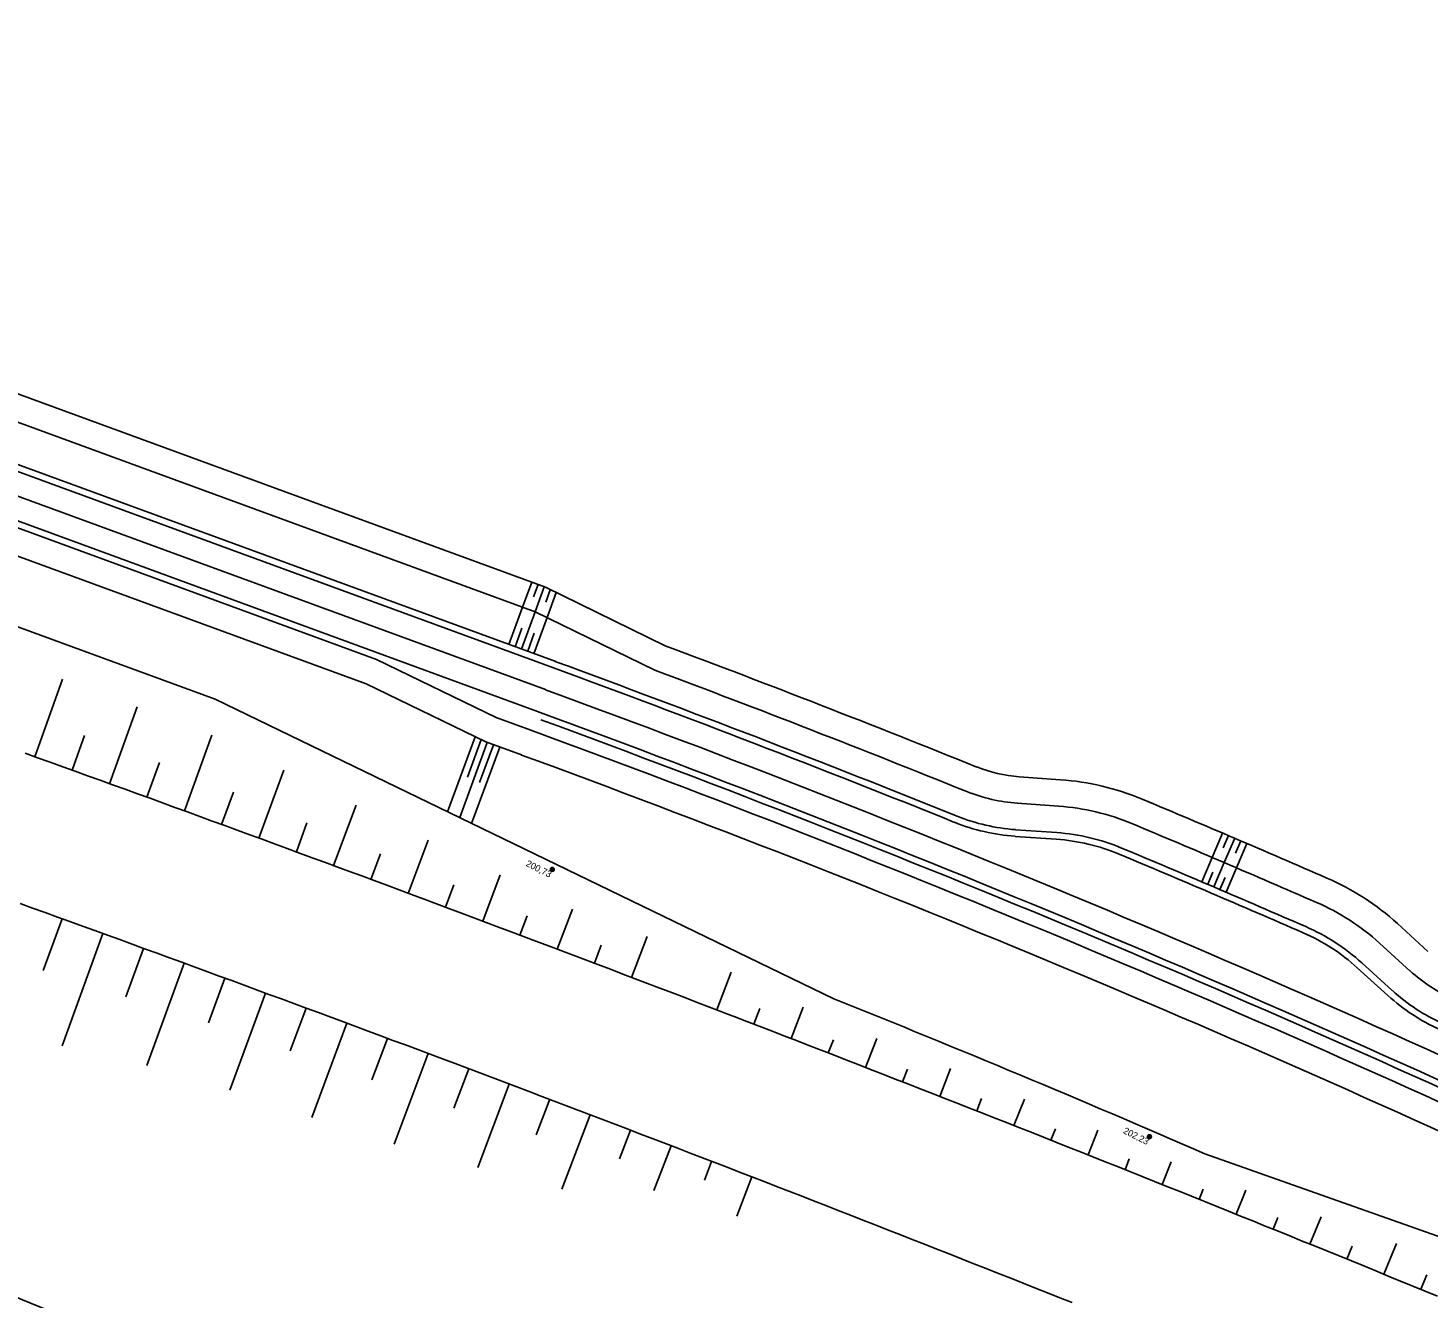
# Model space of a CAD drawing. Extents: x -552278 to -547230, y -1151007 to -1148251.
# Drawn here: x -550769.8 to -550664.2, y -1148841.8 to -1148746 of the extents above; entities that cross this region are included whole.
import ezdxf

# ---------------------------------------------------------------- set-up
doc = ezdxf.new("R2010")
doc.units = 0
doc.layers.add('SO221815_VYSKOPIS', color=7, linetype='Continuous')
doc.layers.add('u_trat navrh', color=7, linetype='Continuous')

# ---------------------------------------------------------------- blocks, each defined once
blk = doc.blocks.new('SO221824_VYSKOPIS')
at = {"layer": 'SO221815_VYSKOPIS'}
for p, q in [((1.2, -0.9), (-1.2, 0.9)), ((0.9, 1.2), (-0.9, -1.2)), ((0.9, 1.2), (0, 0)), ((0, 0), (1.2, -0.9))]:
    blk.add_line(p, q, dxfattribs=at)
blk.add_lwpolyline([(-0.9, -1.2), (0, 0), (-1.2, 0.9)], dxfattribs=at)
blk.add_circle((0, 0), 1.5, dxfattribs=at)
for start, end in [(145.362, 235.1538), (325.362, 55.1538)]:
    blk.add_arc((0, 0), 1.5, start, end, dxfattribs=at)

msp = doc.modelspace()

# ---------------------------------------------------------------- linework, layer by layer
at = {"layer": 'u_trat navrh'}
for p, q in [((-550730.77, -1148788.22), (-550845.88, -1148746.02)), ((-550731.56, -1148790.07), (-550846.57, -1148747.9)), ((-550730.17, -1148794.3), (-550847.77, -1148751.19)), ((-550730, -1148793.83), (-550847.6, -1148750.72)), ((-550730.77, -1148795.94), (-550848.38, -1148752.83)), ((-550743.53, -1148793.66), (-550849.15, -1148754.94)), ((-550731.38, -1148797.59), (-550848.98, -1148754.47)), ((-550744.31, -1148795.51), (-550849.84, -1148756.82)), ((-550732.5, -1148789.72), (-550731.81, -1148787.84)), ((-550731.68, -1148788.95), (-550731.34, -1148788.02)), ((-550731.56, -1148790.07), (-550730.87, -1148788.19)), ((-550721.74, -1148792.63), (-550730.77, -1148788.22)), ((-550730.76, -1148789.34), (-550730.42, -1148788.4)), ((-550730.66, -1148790.51), (-550729.96, -1148788.62)), ((-550755.7, -1148796.66), (-550774.11, -1148789.91)), ((-550733.53, -1148792.54), (-550732.5, -1148789.72)), ((-550732.59, -1148792.88), (-550731.56, -1148790.07)), ((-550722.53, -1148794.47), (-550731.56, -1148790.07)), ((-550733.06, -1148792.71), (-550732.55, -1148791.3)), ((-550731.65, -1148793.23), (-550730.66, -1148790.51)), ((-550732.12, -1148793.05), (-550731.62, -1148791.67)), ((-550743.53, -1148793.66), (-550734.49, -1148798.05)), ((-550769.31, -1148801), (-550767.22, -1148795.16)), ((-550744.31, -1148795.51), (-550735.27, -1148799.89)), ((-550763.67, -1148803.04), (-550761.57, -1148797.23)), ((-550755.7, -1148796.66), (-550709.03, -1148819.26)), ((-550731.89, -1148799), (-550734.49, -1148798.05)), ((-550766.49, -1148802.02), (-550765.55, -1148799.4)), ((-550758.02, -1148805.08), (-550755.95, -1148799.38)), ((-550736.08, -1148799.49), (-550738.16, -1148805.16)), ((-550735.63, -1148799.71), (-550736.67, -1148802.54)), ((-550735.17, -1148799.92), (-550737.25, -1148805.59)), ((-550734.23, -1148800.27), (-550736.35, -1148806.03)), ((-550734.7, -1148800.1), (-550735.75, -1148802.95)), ((-550732.58, -1148800.87), (-550735.27, -1148799.89)), ((-550760.84, -1148804.06), (-550759.9, -1148801.45)), ((-550752.39, -1148807.14), (-550750.51, -1148802.02)), ((-550695.04, -1148802.52), (-550691.92, -1148802.74)), ((-550755.21, -1148806.11), (-550754.32, -1148803.68)), ((-550746.76, -1148809.22), (-550745.07, -1148804.65)), ((-550695.18, -1148804.51), (-550692.06, -1148804.73)), ((-550749.57, -1148808.18), (-550748.77, -1148806)), ((-550695.35, -1148807.01), (-550692.24, -1148807.23)), ((-550695.32, -1148806.51), (-550692.2, -1148806.73)), ((-550680.49, -1148808.6), (-550679.7, -1148806.76)), ((-550679.64, -1148807.87), (-550679.24, -1148806.95)), ((-550679.57, -1148808.99), (-550678.78, -1148807.15)), ((-550741.13, -1148811.31), (-550739.63, -1148807.29)), ((-550678.72, -1148808.27), (-550678.32, -1148807.35)), ((-550678.65, -1148809.38), (-550677.86, -1148807.54)), ((-550743.94, -1148810.26), (-550743.23, -1148808.33)), ((-550681.27, -1148810.44), (-550680.49, -1148808.6)), ((-550680.35, -1148810.83), (-550679.57, -1148808.99)), ((-550735.51, -1148813.41), (-550734.2, -1148809.92)), ((-550680.81, -1148810.63), (-550680.42, -1148809.71)), ((-550679.89, -1148811.03), (-550679.5, -1148810.11)), ((-550679.43, -1148811.22), (-550678.65, -1148809.38)), ((-550738.32, -1148812.35), (-550737.69, -1148810.67)), ((-550767.25, -1148813.23), (-550768.66, -1148817.14)), ((-550732.7, -1148814.46), (-550732.15, -1148813.01)), ((-550729.89, -1148815.52), (-550728.75, -1148812.5)), ((-550764.17, -1148814.34), (-550767.25, -1148822.82)), ((-550724.28, -1148817.65), (-550723.11, -1148814.57)), ((-550666.51, -1148813.59), (-550664.2, -1148815.69)), ((-550761.1, -1148815.46), (-550762.43, -1148819.11)), ((-550727.08, -1148816.58), (-550726.57, -1148815.21)), ((-550667.85, -1148815.07), (-550665.54, -1148817.17)), ((-550758.03, -1148816.58), (-550760.86, -1148824.3)), ((-550669.2, -1148816.55), (-550666.89, -1148818.65)), ((-550754.96, -1148817.7), (-550756.2, -1148821.08)), ((-550717.86, -1148820.1), (-550716.77, -1148817.25)), ((-550669.53, -1148816.92), (-550667.22, -1148819.02)), ((-550751.89, -1148818.83), (-550754.59, -1148826.15)), ((-550748.83, -1148819.97), (-550750.03, -1148823.2)), ((-550715.05, -1148821.18), (-550714.6, -1148820.01)), ((-550712.25, -1148822.26), (-550711.33, -1148819.89)), ((-550745.76, -1148821.11), (-550748.4, -1148828.21)), ((-550742.7, -1148822.25), (-550743.87, -1148825.39)), ((-550709.44, -1148823.35), (-550709.05, -1148822.35)), ((-550706.64, -1148824.44), (-550705.79, -1148822.25)), ((-550739.63, -1148823.39), (-550742.2, -1148830.23)), ((-550736.57, -1148824.54), (-550737.69, -1148827.51)), ((-550703.84, -1148825.53), (-550703.46, -1148824.57)), ((-550701.03, -1148826.63), (-550700.21, -1148824.53)), ((-550733.51, -1148825.7), (-550735.89, -1148831.99)), ((-550730.46, -1148826.85), (-550731.47, -1148829.54)), ((-550698.23, -1148827.73), (-550697.87, -1148826.8)), ((-550695.44, -1148828.83), (-550694.65, -1148826.84)), ((-550727.4, -1148828.02), (-550729.54, -1148833.63)), ((-550724.35, -1148829.18), (-550725.18, -1148831.35)), ((-550692.64, -1148829.94), (-550692.29, -1148829.07)), ((-550689.84, -1148831.05), (-550689.1, -1148829.18)), ((-550721.29, -1148830.35), (-550722.6, -1148833.74)), ((-550687.05, -1148832.16), (-550686.73, -1148831.35)), ((-550681.03, -1148830.96), (-550658.23, -1148839.02)), ((-550718.24, -1148831.53), (-550718.79, -1148832.94)), ((-550684.25, -1148833.28), (-550683.57, -1148831.56)), ((-550715.21, -1148832.7), (-550716.35, -1148835.66)), ((-550681.46, -1148834.4), (-550681.16, -1148833.63)), ((-550678.67, -1148835.52), (-550677.94, -1148833.71)), ((-550673.1, -1148837.77), (-550672.26, -1148835.72)), ((-550675.88, -1148836.64), (-550675.53, -1148835.77)), ((-550667.52, -1148840.04), (-550666.58, -1148837.73)), ((-550670.31, -1148838.91), (-550669.91, -1148837.92)), ((-550664.74, -1148841.18), (-550664.29, -1148840.08))]:
    msp.add_line(p, q, dxfattribs=at)
for points in [[(-550770.03, -1148800.74), (-550769.09, -1148801.08), (-550768.15, -1148801.42), (-550767.2, -1148801.76), (-550766.26, -1148802.1), (-550765.32, -1148802.44), (-550764.38, -1148802.78), (-550763.44, -1148803.12), (-550762.49, -1148803.46), (-550761.55, -1148803.8), (-550760.61, -1148804.14), (-550759.67, -1148804.48), (-550758.73, -1148804.83), (-550757.79, -1148805.17), (-550756.85, -1148805.51), (-550755.91, -1148805.86), (-550754.97, -1148806.2), (-550754.03, -1148806.54), (-550753.09, -1148806.89), (-550752.15, -1148807.23), (-550751.21, -1148807.58), (-550750.27, -1148807.92), (-550749.33, -1148808.27), (-550748.39, -1148808.62), (-550747.45, -1148808.96), (-550746.51, -1148809.31), (-550745.57, -1148809.66), (-550744.63, -1148810), (-550743.69, -1148810.35), (-550742.75, -1148810.7), (-550741.81, -1148811.05), (-550740.88, -1148811.4), (-550739.94, -1148811.75), (-550739, -1148812.1), (-550738.06, -1148812.45), (-550737.12, -1148812.8), (-550736.19, -1148813.15), (-550735.25, -1148813.5), (-550734.31, -1148813.86), (-550733.37, -1148814.21), (-550732.44, -1148814.56), (-550731.5, -1148814.91), (-550730.56, -1148815.27), (-550729.62, -1148815.62), (-550728.69, -1148815.98), (-550727.75, -1148816.33), (-550726.82, -1148816.69), (-550725.88, -1148817.04), (-550724.94, -1148817.4), (-550724.01, -1148817.75), (-550723.07, -1148818.11), (-550722.14, -1148818.47), (-550721.2, -1148818.82), (-550720.27, -1148819.18), (-550719.33, -1148819.54), (-550718.39, -1148819.9), (-550717.46, -1148820.26), (-550717.16, -1148820.37), (-550716.53, -1148820.61), (-550715.59, -1148820.97), (-550714.66, -1148821.33), (-550713.72, -1148821.69), (-550712.79, -1148822.05), (-550711.85, -1148822.42), (-550710.92, -1148822.78), (-550709.99, -1148823.14), (-550709.05, -1148823.5), (-550708.12, -1148823.86), (-550707.19, -1148824.23), (-550706.25, -1148824.59), (-550705.32, -1148824.95), (-550704.39, -1148825.32), (-550703.45, -1148825.68), (-550702.52, -1148826.05), (-550701.59, -1148826.41), (-550700.66, -1148826.78), (-550699.72, -1148827.14), (-550698.79, -1148827.51), (-550697.86, -1148827.87), (-550696.93, -1148828.24), (-550696, -1148828.61), (-550695.07, -1148828.98), (-550694.13, -1148829.34), (-550693.2, -1148829.71), (-550692.27, -1148830.08), (-550691.34, -1148830.45), (-550690.41, -1148830.82), (-550689.48, -1148831.19), (-550688.55, -1148831.56), (-550687.62, -1148831.93), (-550686.69, -1148832.3), (-550685.76, -1148832.67), (-550684.83, -1148833.05), (-550683.9, -1148833.42), (-550682.97, -1148833.79), (-550682.04, -1148834.16), (-550681.11, -1148834.54), (-550680.18, -1148834.91), (-550679.25, -1148835.28), (-550678.33, -1148835.66), (-550677.4, -1148836.03), (-550676.47, -1148836.41), (-550675.54, -1148836.78), (-550674.61, -1148837.16), (-550673.68, -1148837.54), (-550672.76, -1148837.91), (-550671.83, -1148838.29), (-550670.9, -1148838.67), (-550669.97, -1148839.04), (-550669.05, -1148839.42), (-550668.12, -1148839.8), (-550667.19, -1148840.18), (-550666.27, -1148840.56), (-550665.34, -1148840.94), (-550664.41, -1148841.32), (-550663.49, -1148841.7)], [(-550770.41, -1148812.08), (-550769.47, -1148812.42), (-550768.53, -1148812.76), (-550767.59, -1148813.1), (-550766.65, -1148813.44), (-550765.71, -1148813.78), (-550764.77, -1148814.12), (-550763.83, -1148814.46), (-550762.89, -1148814.8), (-550761.96, -1148815.14), (-550761.02, -1148815.49), (-550760.08, -1148815.83), (-550759.14, -1148816.17), (-550758.2, -1148816.51), (-550757.27, -1148816.86), (-550756.33, -1148817.2), (-550755.39, -1148817.55), (-550754.45, -1148817.89), (-550753.52, -1148818.24), (-550752.58, -1148818.58), (-550751.64, -1148818.93), (-550750.7, -1148819.27), (-550749.77, -1148819.62), (-550748.83, -1148819.97), (-550747.89, -1148820.31), (-550746.96, -1148820.66), (-550746.02, -1148821.01), (-550745.09, -1148821.36), (-550744.15, -1148821.7), (-550743.21, -1148822.05), (-550742.28, -1148822.4), (-550741.34, -1148822.75), (-550740.41, -1148823.1), (-550739.47, -1148823.45), (-550738.54, -1148823.8), (-550737.6, -1148824.16), (-550736.67, -1148824.51), (-550735.73, -1148824.86), (-550734.8, -1148825.21), (-550733.86, -1148825.56), (-550732.93, -1148825.92), (-550732, -1148826.27), (-550731.06, -1148826.63), (-550730.13, -1148826.98), (-550729.19, -1148827.33), (-550728.26, -1148827.69), (-550727.33, -1148828.04), (-550726.39, -1148828.4), (-550725.46, -1148828.76), (-550724.53, -1148829.11), (-550723.6, -1148829.47), (-550722.66, -1148829.83), (-550721.73, -1148830.18), (-550720.8, -1148830.54), (-550720.73, -1148830.57), (-550719.87, -1148830.9), (-550718.93, -1148831.26), (-550718, -1148831.62), (-550717.07, -1148831.98), (-550716.14, -1148832.34), (-550715.21, -1148832.7), (-550714.28, -1148833.06), (-550713.34, -1148833.42), (-550712.41, -1148833.78), (-550711.48, -1148834.14), (-550710.55, -1148834.5), (-550709.62, -1148834.87), (-550708.69, -1148835.23), (-550707.76, -1148835.59), (-550706.83, -1148835.96), (-550705.9, -1148836.32), (-550704.97, -1148836.69), (-550704.04, -1148837.05), (-550703.11, -1148837.42), (-550702.18, -1148837.78), (-550701.25, -1148838.15), (-550700.32, -1148838.51), (-550699.39, -1148838.88), (-550698.47, -1148839.25), (-550697.54, -1148839.61), (-550696.61, -1148839.98), (-550695.68, -1148840.35), (-550694.75, -1148840.72), (-550693.82, -1148841.09), (-550692.9, -1148841.46), (-550691.97, -1148841.82), (-550691.04, -1148842.19)]]:
    msp.add_lwpolyline(points, dxfattribs=at)
for centre, radius, start, end in [((-551074.98, -1149734.84), 1006.25, 68.01222, 69.44873), ((-551074.98, -1149734.84), 1001.75, 68.01222, 69.86671), ((-551074.98, -1149734.84), 1002.25, 68.01222, 69.86671), ((-551074.98, -1149734.84), 1004.25, 68.01222, 69.45415), ((-551074.98, -1149734.84), 1000, 64.80614, 69.86671), ((-551074.98, -1149734.84), 998.25, 64.80614, 69.86671), ((-551074.98, -1149734.84), 997.75, 64.80614, 69.84139), ((-551074.98, -1149734.84), 996.75, 64.80614, 69.86671), ((-551074.98, -1149734.84), 994.75, 64.80614, 69.86671), ((-550694.3, -1148792.04), 10.5, 248.0122, 265.9747), ((-550693.29, -1148822.19), 19.5, 67.3044, 85.9747), ((-550694.3, -1148792.04), 12.5, 248.0122, 265.9747), ((-550693.29, -1148822.19), 17.5, 67.3044, 85.9747), ((-551074.98, -1149734.84), 1008.75, 66.44292, 67.30444), ((-551056.59, -1149542.18), 756.5, 67.46341, 76.89047), ((-550694.3, -1148792.04), 15, 248.0122, 265.9747), ((-550694.3, -1148792.04), 14.5, 248.0122, 265.9747), ((-551074.98, -1149734.84), 1006.75, 66.44292, 67.30444), ((-550693.29, -1148822.19), 15.5, 67.3044, 85.9747), ((-551056.59, -1149542.18), 754, 51.79075, 76.89047), ((-550693.29, -1148822.19), 15, 67.3044, 85.9747), ((-551074.98, -1149734.84), 1004.75, 66.44292, 67.30444), ((-551056.59, -1149542.18), 753.25, 51.79075, 76.89047), ((-551074.98, -1149734.84), 1004.25, 66.44292, 67.30444), ((-550679.61, -1148828.03), 19.5, 47.7726, 66.4429), ((-551056.59, -1149542.18), 750, 47.42068, 76.89047), ((-550679.61, -1148828.03), 17.5, 47.7726, 66.4429), ((-550679.61, -1148828.03), 15, 47.7726, 66.4429), ((-550679.61, -1148828.03), 15.5, 47.7726, 66.4429), ((-550657.14, -1148807.91), 12.5, 227.7726, 245.7351), ((-550657.14, -1148807.91), 14.5, 227.7726, 245.7351), ((-551074.98, -1149734.84), 986, 66.45038, 68.21372), ((-550657.14, -1148807.91), 15, 227.7726, 245.7351), ((-551056.59, -1149542.18), 746.75, 47.42068, 72.23343), ((-551056.59, -1149542.18), 746, 47.42068, 72.23343)]:
    msp.add_arc(centre, radius, start, end, dxfattribs=at)

# ---------------------------------------------------------------- block references
at = {"layer": 'u_trat navrh', "xscale": 0.1, "yscale": 0.09999999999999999, "rotation": -31.851985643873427}
for p in [(-550730.26, -1148809.51), (-550685.21, -1148829.67)]:
    msp.add_blockref('SO221824_VYSKOPIS', p, dxfattribs=at)

# ---------------------------------------------------------------- texts
at = {"layer": 'u_trat navrh'}
for s, p in [('200,73', (-550732.3, -1148809.22)), ('202,23', (-550687.24, -1148829.38))]:
    msp.add_text(s, height=0.5, rotation=333.2568, dxfattribs=at).set_placement(p)

doc.saveas('drawing.dxf')
